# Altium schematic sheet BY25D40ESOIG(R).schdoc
size 127 x 101 mm
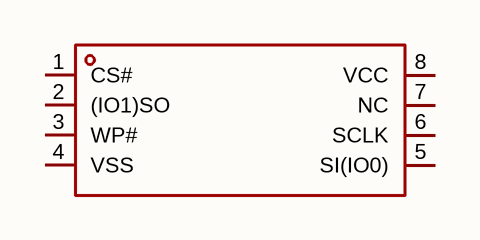
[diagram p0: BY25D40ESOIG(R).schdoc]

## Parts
U?  by25d40esoig(r)  [TSSOP-8_L4.4-W3.0-P0.65-LS6.4-BL-3]  (value not drawn)

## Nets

Not connected (* = marked no-connect by the designer): U? 1(CS#) 2((IO1)SO) 3(WP#) 4(VSS) 5(SI(IO0)) 6(SCLK) 7(NC) 8(VCC)

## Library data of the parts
U? = by25d40esoig(r): 接口类型:SPI;存储容量:4Mbit;时钟频率(fc):108MHz;; Manufacturer: BOYAMICRO(博雅); AddInBom: yes; ModelId: 03fc033f402846a5ab66f50ee4246a8b; ModelTransform: 118.11,251.968,0,0,0,0,0,0,0; Interface: SPI; Memory Size: 4Mbit; Clock Frequency: 108MHz; Voltage - Supply: 2.7V~3.6V; Standby Supply Current: 5uA; Program / Erase Cycles: 100000次; Page Programming Time (Tpp): 800us; Block Erase Time(tBE): 300ms; Data Retention - TDR (Year): 20年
